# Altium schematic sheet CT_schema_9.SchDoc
size 147 x 119 mm
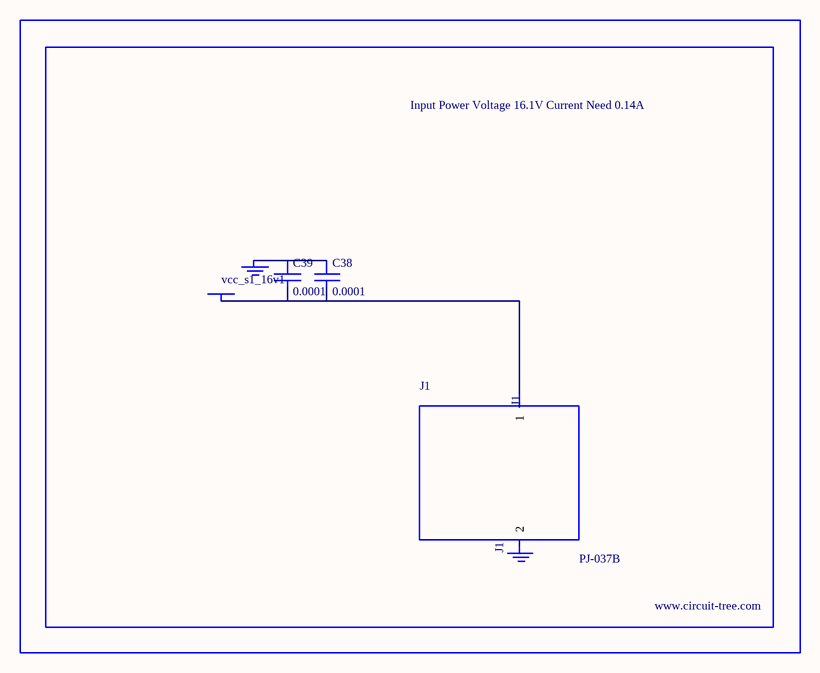
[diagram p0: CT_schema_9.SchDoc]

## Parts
BORDER8  (no value)
C38  0.0001  [EXV-9H]
C39  0.0001  [EXV-9H]
GND_INSTANCE_8_0  (no value)
GND_INSTANCE_8_1  (no value)
J1  PJ-037B  [PJ-037B_PACKAGE]
POWER_INSTANCE_8_0  vcc_s1_16v1

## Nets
NetC38_1: C38.1 C39.1 GND_INSTANCE_8_0.0(GND)
NetC38_2: C38.2 C39.2 J1.1 POWER_INSTANCE_8_0.0(PWR)

Not connected (* = marked no-connect by the designer): GND_INSTANCE_8_1 0(GND); J1 2

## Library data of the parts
BORDER8 = BORDER_PAGE8
C38 C39 = EDK107M035A9HAA
GND_INSTANCE_8_0 GND_INSTANCE_8_1 = GND
POWER_INSTANCE_8_0 = PWR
